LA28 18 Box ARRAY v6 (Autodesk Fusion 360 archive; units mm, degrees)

design "LA28 18 Box ARRAY" references "LA28 RF1 Sheet Metal Assembly", "LA28 TOUR BLOCK"
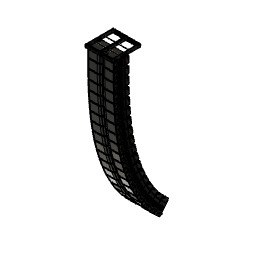
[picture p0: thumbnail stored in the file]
component_insert "Component Insert1"
as_built_joint "As-built1"
component_insert "Component Insert2"
joint "Assemble1" alignAngle 0 alignOffsetX 0 alignOffsetY 0 alignOffsetZ 5.08
component_insert "Component Insert3"
joint "Assemble2" alignAngle -0.5 alignOffsetX 0 alignOffsetY 0 alignOffsetZ 5.08
component_insert "Component Insert4"
component_insert "Component Insert5"
joint "Assemble3" alignAngle -0.5 alignOffsetX 0 alignOffsetY 0 alignOffsetZ 5.08
joint "Assemble4" alignAngle -1 alignOffsetX 0 alignOffsetY 0 alignOffsetZ 5.08
component_insert "Component Insert6"
component_insert "Component Insert7"
component_insert "Component Insert8"
joint "Assemble5" alignAngle -1.5 alignOffsetX 0 alignOffsetY 0 alignOffsetZ 5.08
joint "Assemble6" alignAngle -1.5 alignOffsetX 0 alignOffsetY 0 alignOffsetZ 5.08
joint "Assemble7" alignAngle -2 alignOffsetX 0 alignOffsetY 0 alignOffsetZ 5.08
component_insert "Component Insert9"
joint "Assemble8" alignAngle -2 alignOffsetX 0 alignOffsetY 0 alignOffsetZ 5.08
component_insert "Component Insert10"
joint "Assemble9" alignAngle -2 alignOffsetX 0 alignOffsetY 0 alignOffsetZ 5.08
component_insert "Component Insert11"
component_insert "Component Insert12"
joint "Assemble10" alignAngle -3 alignOffsetX 0 alignOffsetY 0 alignOffsetZ 5.08
joint "Assemble11" alignAngle -3 alignOffsetX 0 alignOffsetY 0 alignOffsetZ 5.08
component_insert "Component Insert13"
joint "Assemble12" alignAngle -3 alignOffsetX 0 alignOffsetY 0 alignOffsetZ 5.08
component_insert "Component Insert14"
component_insert "Component Insert15"
joint "Assemble13" alignAngle -3 alignOffsetX 0 alignOffsetY 0 alignOffsetZ 5.08
joint "Assemble14" alignAngle -4 alignOffsetX 0 alignOffsetY 0 alignOffsetZ 5.08
component_insert "Component Insert16"
component_insert "Component Insert17"
joint "Assemble15" alignAngle -4 alignOffsetX 0 alignOffsetY 0 alignOffsetZ 5.08
joint "Assemble16" alignAngle -5 alignOffsetX 0 alignOffsetY 0 alignOffsetZ 5.08
component_insert "Component Insert18"
component_insert "Component Insert19"
joint "Assemble17" alignAngle -5 alignOffsetX 0 alignOffsetY 0 alignOffsetZ 5.08
joint "Assemble18" alignAngle -7 alignOffsetX 0 alignOffsetY 0 alignOffsetZ 5.08

design "la28RF1 SHEET METAL ASSEMBLY.SLDASM"
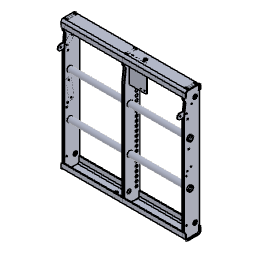
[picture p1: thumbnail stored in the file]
named bodies: "Cut-Extrude3", "Cut-Extrude2", "Mirror2", "Boss-Extrude1"

design "LA28 TOUR BLOCK" references "LA28 TOUR BLOCK.sldprt"
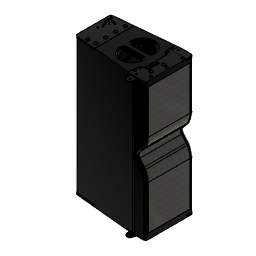
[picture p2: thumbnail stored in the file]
step "WorkingModel"
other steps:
derived_base_feature "Derived Base Feature" bodies "Fillet3"
named bodies: "Fillet3"

design "LA28 RF1 Sheet Metal Assembly" references "la28RF1 SHEET METAL ASSEMBLY.SLDASM"
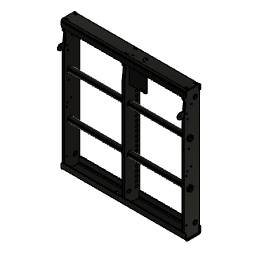
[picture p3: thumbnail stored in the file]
step "WorkingModel"
derived_instance "DerivedInstance1"
derived_instance "DerivedInstance2"
derived_instance "DerivedInstance3"
derived_instance "DerivedInstance4"
derived_instance "DerivedInstance5"
derived_instance "DerivedInstance6"
derived_instance "DerivedInstance7"
as_built_joint "As-built1"
offset_faces "OffsetFaces1" distance 0.7595 (= "0.1644 in - 0.1345 in")
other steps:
derived_base_feature "Derived Base Feature1"
derived_base_feature "Derived Base Feature1" bodies "Cut-Extrude3"
derived_base_feature "Derived Base Feature1" bodies "Cut-Extrude3"
derived_base_feature "Derived Base Feature1" bodies "Boss-Extrude1"
derived_base_feature "Derived Base Feature1" bodies "Cut-Extrude2"
derived_base_feature "Derived Base Feature1" bodies "Boss-Extrude1"
derived_base_feature "Derived Base Feature1" bodies "Cut-Extrude2"
derived_base_feature "Derived Base Feature1" bodies "Mirror2"
create_component "CreateComponent1"
create_component "CreateComponent2"
create_component "CreateComponent3"
create_component "CreateComponent4"
create_component "CreateComponent5"
create_component "CreateComponent6"
create_component "CreateComponent7"
named bodies: "Cut-Extrude3", "Cut-Extrude2", "Mirror2", "Boss-Extrude1"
